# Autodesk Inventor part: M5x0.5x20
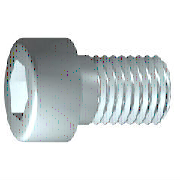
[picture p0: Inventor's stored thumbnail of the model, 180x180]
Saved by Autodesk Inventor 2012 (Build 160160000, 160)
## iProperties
IsCustomPart: 0
Company: 한국ATC센터
Created: 2014-07
Part Number: M5x0.5x20
Material: Steel, Mild
Description: 6각머리 태핑 나사
Document SubType Name: Modeling
Standard: KS B 1003
Designer: KYOUNG IL JANG
Standards Organization: KS
Language: ko-KR
Size Designation: M 5 x 20
Categories: <MemberInstance><Categories><Category DisplayName="조임쇠" InternalName="e4da775c-781d-43d5-af7c-5136215cf5a6" Mnemonic="FSTN"><Category DisplayName="볼트" InternalN
Density: 7.86 g/cm^3
Mass: 4.9629 g
Surface Area: 5.88238 cm^2
Volume: 0.631412 cm^3
Author: KYOUNG IL JANG
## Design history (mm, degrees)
workplane "Work Plane1"
fillet "Fillet2" dims "d30" = 0.1 (= R)
revolve "본체" stored, may be unused: angle "d10" = 90 deg
sketch "스케치2"
  geometry: L1 (0, -5.95)-(0, 5.95) reference; L2 (-5.95, 0)-(5.95, 0) reference; L3 (2.309, 0)-(1.155, -2); L4 (1.155, -2)-(-1.155, -2); L5 (-1.155, -2)-(-2.309, 0); L6 (-2.309, 0)-(-1.155, 2); L7 (-1.155, 2)-(1.155, 2); L8 (1.155, 2)-(2.309, 0); 2 further points
  constraints: 12 end point, 1 coincident, 1 horizontal alignment, 1 point on line, 12 other
extrude "슬롯" join sketch "스케치2" stored distance "d11" = 10; taper "d12" = 0 deg
body "Solid1"
fillet "모깎기1" dims "d17" = 0.5 (= RR)
feature "스레드" dims "d13" = 18 (= GEL), "d14" = 0
chamfer "모따기1" distance "d15" = 0.49076 (= -0.5 x SPD + 0.5 x GD); stored, may be unused: second distance "d16" = 0.49076 (= GUL), angle "d27" = 45 deg
sketch "스케치1"
  geometry: L1 (-1.167, 0)-(20, 0); L2 (20, 0)-(20, 2.5); L3 (20, 2.5)-(2, 2.5); L4 (2, 2.5)-(1.509, 2.5); L5 (1.509, 2.5)-(0, 2.5); L6 (0, 2.5)-(0, 4.25); L7 (0, 4.25)-(-5, 4.25); L8 (-5, 4.25)-(-5, 2.309); L9 (-5, 2.309)-(-2.5, 2.309); L10 (-2.5, 2.309)-(-1.167, 0); L11 (-10, 0)-(25, 0) reference; L12 (0, -0.85)-(0, 5.1) reference; L13 (2, 2.5)-(0, 2.5)
  constraints: 22 end point, 6 parallel, 2 collinear, 2 perpendicular, 1 horizontal, 1 point on line
  dimensions: "d1" = 18 distance from line of L3.end L2 (= GEL); "d2" = 0.49086 distance of L4.end L3.end (computed from GAL); "d3" = 5 distance between parallel lines of L8 L6 (= KOH); "d4" = 2.5 distance of L8.end L9.end (= INTI); "d5" = 60 deg angle of L10 L1; "d6" = 5 diameter of L3 L1 (= GD); "d7" = 5 diameter of L5 L1 (= BDM); "d8" = 4.6188 diameter of L9 L1 (= 1.1547 x SW); "d9" = 8.5 diameter of L7 L1 (= KOD); "d26" = 20 distance between parallel lines of L12 L2 (= NLG)
other parameters: "GD" = 5 (= NND) [user parameter; used in 2 equation terms], "NLG" = 20 [user parameter; used in 1 equation term], "GEL" = 18 [user parameter; used in 2 equation terms], "KOD" = 8.5 [user parameter; used in 1 equation term], "KOH" = 5 [user parameter; used in 1 equation term], "INTI" = 2.5 [user parameter; used in 1 equation term], "GAL" = 0.49076 (= 0.61345 x PTC) [user parameter; used in 1 equation term], "GUL" = 0.49076 (= 0.61345 x PTC) [user parameter; used in 1 equation term], "BDM" = 5 (= NND) [user parameter; used in 1 equation term], "SW" = 4 [user parameter; used in 2 equation terms], "RR" = 0.5 [user parameter; used in 1 equation term], "SPD" = 4.01848 (= NND - 1.2269 x PTC) [user parameter; used in 1 equation term], "d19" = 0, "d28" = 0, "d29" = 0, "R" = 0.1 [user parameter; used in 1 equation term], "PHH" = 0.2 [user parameter], "GD1" = 4.01848 (= THREADDIA - 1.2269 x PTC) [user parameter], "THREADDIA" = 5 [user parameter; used in 1 equation term], "FAWI" = 45 deg [user parameter], "TPU" = 12.5 (computed from PTC) [user parameter], "PTC" = 0.8 [user parameter; used in 5 equation terms], "NND" = 5 [user parameter; used in 3 equation terms], "TOA" = 30 deg [user parameter], "E0" = 4.62 (= 1.155 x SW) [user parameter]
